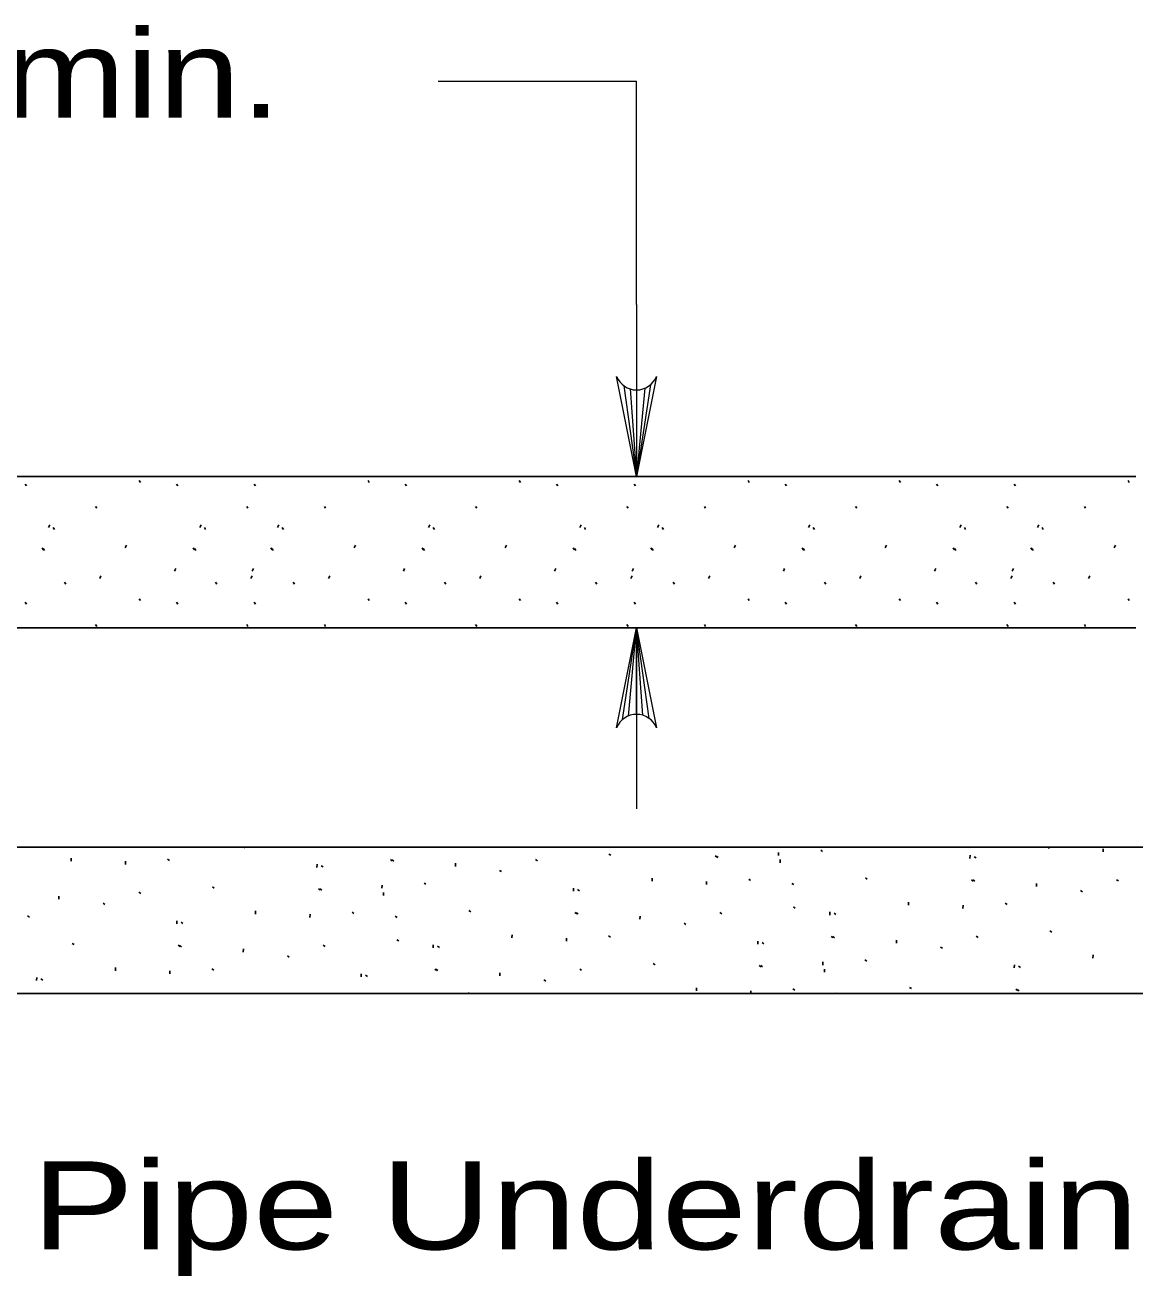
# Model space of a CAD drawing. Extents: x 1083.1 to 1117.1, y 697.4 to 741.4.
# Drawn here: x 1095.513 to 1097.478, y 711.657 to 713.873 of the extents above; entities that cross this region are included whole.
import ezdxf
from ezdxf.enums import TextEntityAlignment as Align

# ---------------------------------------------------------------- set-up
doc = ezdxf.new("R2010")
doc.units = 0
doc.header["$LTSCALE"] = 0.062
doc.layers.add('1', color=7, linetype='Continuous', lineweight=13)

msp = doc.modelspace()

# ---------------------------------------------------------------- linework, layer by layer
at = {"layer": '1'}
for p, q in [((1096.2445, 713.77358), (1096.59592, 713.77358)), ((1096.59592, 713.37825), (1096.59592, 713.77358)), ((1096.59592, 713.37825), (1096.59592, 713.07375)), ((1096.62075, 713.23592), (1096.59592, 713.07375)), ((1096.5735, 713.234), (1096.59592, 713.07375)), ((1096.58458, 713.22858), (1096.59592, 713.07375)), ((1096.61033, 713.22975), (1096.59592, 713.07375)), ((1096.59592, 713.22692), (1096.59592, 713.07375)), ((1096.57117, 712.64308), (1096.59592, 712.80517)), ((1096.58158, 712.64917), (1096.59592, 712.80517)), ((1096.59592, 712.80517), (1096.59592, 712.485)), ((1096.59592, 712.652), (1096.59592, 712.80517)), ((1096.60725, 712.65042), (1096.59592, 712.80517)), ((1096.61833, 712.64492), (1096.59592, 712.80517))]:
    msp.add_line(p, q, dxfattribs=at)
at = {"layer": '1', "lineweight": 25}
for p, q in [((1095.5135, 713.06008), (1095.51575, 713.05683)), ((1095.71517, 713.06617), (1095.71742, 713.06283)), ((1095.78117, 713.06008), (1095.7835, 713.05683)), ((1095.91867, 713.06008), (1095.921, 713.05683)), ((1096.12042, 713.06617), (1096.12258, 713.06283)), ((1096.18642, 713.06008), (1096.18867, 713.05683)), ((1096.38808, 713.06617), (1096.39033, 713.06283)), ((1096.45408, 713.06008), (1096.45633, 713.05683)), ((1096.59158, 713.06008), (1096.59392, 713.05683)), ((1096.79333, 713.06617), (1096.7955, 713.06283)), ((1096.85933, 713.06008), (1096.86158, 713.05683)), ((1097.061, 713.06617), (1097.06325, 713.06283)), ((1097.127, 713.06008), (1097.12933, 713.05683)), ((1097.2645, 713.06008), (1097.26683, 713.05683)), ((1097.46625, 713.06617), (1097.46842, 713.06283)), ((1095.63783, 713.0205), (1095.64017, 713.01708)), ((1095.90558, 713.0205), (1095.90783, 713.01708)), ((1096.04308, 713.0205), (1096.04533, 713.01708)), ((1096.31075, 713.0205), (1096.31308, 713.01708)), ((1096.5785, 713.0205), (1096.58075, 713.01708)), ((1096.716, 713.0205), (1096.71825, 713.01708)), ((1096.98367, 713.0205), (1096.986, 713.01708)), ((1097.25142, 713.0205), (1097.25367, 713.01708)), ((1097.38892, 713.0205), (1097.39117, 713.01708)), ((1095.55475, 712.98292), (1095.557, 712.988)), ((1095.56292, 712.98292), (1095.56517, 712.97967)), ((1095.8225, 712.98292), (1095.82467, 712.988)), ((1095.83058, 712.98292), (1095.83283, 712.97967)), ((1095.96, 712.98292), (1095.96217, 712.988)), ((1095.96808, 712.98292), (1095.97042, 712.97967)), ((1096.22767, 712.98292), (1096.22992, 712.988)), ((1096.23583, 712.98292), (1096.23808, 712.97967)), ((1096.49542, 712.98292), (1096.49758, 712.988)), ((1096.5035, 712.98292), (1096.50575, 712.97967)), ((1096.63292, 712.98292), (1096.63508, 712.988)), ((1096.641, 712.98292), (1096.64333, 712.97967)), ((1096.90058, 712.98292), (1096.90283, 712.988)), ((1096.90867, 712.98292), (1096.911, 712.97967)), ((1097.16833, 712.98292), (1097.1705, 712.988)), ((1097.17642, 712.98292), (1097.17867, 712.97967)), ((1097.30583, 712.98292), (1097.308, 712.988)), ((1097.31392, 712.98292), (1097.31617, 712.97967)), ((1095.69058, 712.947), (1095.69283, 712.952)), ((1096.09575, 712.947), (1096.09808, 712.952)), ((1096.3635, 712.947), (1096.36575, 712.952)), ((1096.76867, 712.947), (1096.771, 712.952)), ((1097.03642, 712.947), (1097.03867, 712.952)), ((1097.44158, 712.947), (1097.44392, 712.952)), ((1095.54308, 712.947), (1095.54525, 712.94358)), ((1095.54525, 712.94575), (1095.5475, 712.94233)), ((1095.81075, 712.947), (1095.813, 712.94358)), ((1095.813, 712.94575), (1095.81517, 712.94233)), ((1095.94825, 712.947), (1095.9505, 712.94358)), ((1095.9505, 712.94575), (1095.95267, 712.94233)), ((1096.216, 712.947), (1096.21817, 712.94358)), ((1096.21817, 712.94575), (1096.22033, 712.94233)), ((1096.48367, 712.947), (1096.48583, 712.94358)), ((1096.48583, 712.94575), (1096.48808, 712.94233)), ((1096.62117, 712.947), (1096.62342, 712.94358)), ((1096.62342, 712.94575), (1096.62558, 712.94233)), ((1096.88892, 712.947), (1096.89108, 712.94358)), ((1096.89108, 712.94575), (1096.89333, 712.94233)), ((1097.15658, 712.947), (1097.15883, 712.94358)), ((1097.15883, 712.94575), (1097.161, 712.94233)), ((1097.29408, 712.947), (1097.29633, 712.94358)), ((1097.29633, 712.94575), (1097.2985, 712.94233)), ((1095.77775, 712.9055), (1095.78, 712.91058)), ((1095.91525, 712.9055), (1095.9175, 712.91058)), ((1096.18292, 712.9055), (1096.18525, 712.91058)), ((1096.45067, 712.9055), (1096.45292, 712.91058)), ((1096.58817, 712.9055), (1096.59042, 712.91058)), ((1096.85583, 712.9055), (1096.85817, 712.91058)), ((1097.12358, 712.9055), (1097.12583, 712.91058)), ((1097.26108, 712.9055), (1097.26333, 712.91058)), ((1095.58275, 712.88617), (1095.585, 712.88283)), ((1095.64533, 712.89267), (1095.6475, 712.89775)), ((1095.8505, 712.88617), (1095.85267, 712.88283)), ((1095.913, 712.89267), (1095.91525, 712.89775)), ((1095.988, 712.88617), (1095.99017, 712.88283)), ((1096.0505, 712.89267), (1096.05275, 712.89775)), ((1096.25567, 712.88617), (1096.25792, 712.88283)), ((1096.31825, 712.89267), (1096.32042, 712.89775)), ((1096.52342, 712.88617), (1096.52558, 712.88283)), ((1096.58592, 712.89267), (1096.58817, 712.89775)), ((1096.66092, 712.88617), (1096.66308, 712.88283)), ((1096.72342, 712.89267), (1096.72567, 712.89775)), ((1096.92858, 712.88617), (1096.93083, 712.88283)), ((1096.99117, 712.89267), (1096.99333, 712.89775)), ((1097.19633, 712.88617), (1097.1985, 712.88283)), ((1097.25883, 712.89267), (1097.26108, 712.89775)), ((1097.33383, 712.88617), (1097.336, 712.88283)), ((1097.39633, 712.89267), (1097.39858, 712.89775)), ((1095.5135, 712.85083), (1095.51575, 712.84758)), ((1095.71517, 712.85692), (1095.71742, 712.85358)), ((1095.78117, 712.85083), (1095.7835, 712.84758)), ((1095.91867, 712.85083), (1095.921, 712.84758)), ((1096.12042, 712.85692), (1096.12258, 712.85358)), ((1096.18642, 712.85083), (1096.18867, 712.84758)), ((1096.38808, 712.85692), (1096.39033, 712.85358)), ((1096.45408, 712.85083), (1096.45633, 712.84758)), ((1096.59158, 712.85083), (1096.59392, 712.84758)), ((1096.79333, 712.85692), (1096.7955, 712.85358)), ((1096.85933, 712.85083), (1096.86158, 712.84758)), ((1097.061, 712.85692), (1097.06325, 712.85358)), ((1097.127, 712.85083), (1097.12933, 712.84758)), ((1097.2645, 712.85083), (1097.26683, 712.84758)), ((1097.46625, 712.85692), (1097.46842, 712.85358)), ((1095.63783, 712.81117), (1095.64017, 712.80783)), ((1095.90558, 712.81117), (1095.90783, 712.80783)), ((1096.04308, 712.81117), (1096.04533, 712.80783)), ((1096.31075, 712.81117), (1096.31308, 712.80783)), ((1096.5785, 712.81117), (1096.58075, 712.80783)), ((1096.716, 712.81117), (1096.71825, 712.80783)), ((1096.98367, 712.81117), (1096.986, 712.80783)), ((1097.25142, 712.81117), (1097.25367, 712.80783)), ((1097.38892, 712.81117), (1097.39117, 712.80783)), ((1090.79808, 712.41658), (1097.47717, 712.41658)), ((1095.90133, 712.41658), (1095.90258, 712.41575)), ((1097.32575, 712.41433), (1097.32583, 712.41658)), ((1098.92075, 712.41658), (1097.47717, 712.41658)), ((1095.5945, 712.392), (1095.59475, 712.3975)), ((1095.76558, 712.3955), (1095.76892, 712.39317)), ((1096.16008, 712.39475), (1096.16342, 712.3925)), ((1096.16258, 712.39442), (1096.16592, 712.39217)), ((1096.41683, 712.39483), (1096.42025, 712.39267)), ((1096.547, 712.40467), (1096.55042, 712.40242)), ((1096.73492, 712.40133), (1096.73817, 712.399)), ((1096.73742, 712.401), (1096.74067, 712.39867)), ((1096.84725, 712.402), (1096.8475, 712.40758)), ((1096.85, 712.38933), (1096.85017, 712.39483)), ((1096.922, 712.41133), (1096.92533, 712.409)), ((1097.18633, 712.39683), (1097.1865, 712.40233)), ((1097.19383, 712.39983), (1097.19725, 712.39767)), ((1097.42208, 712.40858), (1097.42233, 712.41408)), ((1095.69083, 712.38617), (1095.69108, 712.39175)), ((1096.03, 712.381), (1096.03017, 712.3865)), ((1096.0375, 712.384), (1096.04083, 712.38183)), ((1096.27525, 712.38275), (1096.27542, 712.38825)), ((1096.35342, 712.37575), (1096.35667, 712.3735)), ((1096.145, 712.344), (1096.14517, 712.3495)), ((1096.21967, 712.35325), (1096.223, 712.351)), ((1096.62342, 712.35633), (1096.62367, 712.36183)), ((1096.71975, 712.3505), (1096.72, 712.35608)), ((1096.7945, 712.35983), (1096.79783, 712.3575)), ((1096.871, 712.35267), (1096.87433, 712.35042)), ((1097.00108, 712.3625), (1097.0045, 712.36017)), ((1097.189, 712.35908), (1097.19225, 712.35683)), ((1097.1915, 712.35875), (1097.19475, 712.3565)), ((1097.30408, 712.34708), (1097.30425, 712.35258)), ((1097.44575, 712.35917), (1097.44908, 712.357)), ((1095.57292, 712.32467), (1095.57308, 712.33017)), ((1095.71458, 712.33683), (1095.71792, 712.33458)), ((1095.84475, 712.34658), (1095.84808, 712.34433)), ((1096.03258, 712.34325), (1096.03592, 712.341)), ((1096.03508, 712.34292), (1096.03842, 712.34058)), ((1096.14775, 712.33125), (1096.14792, 712.33675)), ((1096.48408, 712.33875), (1096.48425, 712.34425)), ((1096.49158, 712.34183), (1096.49492, 712.33958)), ((1097.38233, 712.34008), (1097.38558, 712.33783)), ((1095.65108, 712.31767), (1095.65433, 712.31542)), ((1096.87367, 712.31092), (1096.877, 712.30867)), ((1097.0775, 712.31408), (1097.07775, 712.31958)), ((1097.17383, 712.30833), (1097.17408, 712.31383)), ((1097.24858, 712.31758), (1097.25192, 712.31533)), ((1095.51742, 712.29525), (1095.52067, 712.29292)), ((1095.78175, 712.28075), (1095.78192, 712.28617)), ((1095.78925, 712.28375), (1095.79258, 712.2815)), ((1095.92117, 712.29825), (1095.92133, 712.30375)), ((1096.0175, 712.29242), (1096.01767, 712.298)), ((1096.09217, 712.30175), (1096.0955, 712.29942)), ((1096.16867, 712.29458), (1096.172, 712.29233)), ((1096.29883, 712.30442), (1096.30217, 712.30208)), ((1096.48667, 712.30108), (1096.49, 712.29875)), ((1096.48917, 712.30067), (1096.4925, 712.29842)), ((1096.60183, 712.289), (1096.602, 712.2945)), ((1096.7435, 712.30108), (1096.74683, 712.29892)), ((1096.93817, 712.29658), (1096.93833, 712.30208)), ((1096.94567, 712.29958), (1096.949, 712.29742)), ((1096.37525, 712.256), (1096.37542, 712.2615)), ((1096.68, 712.282), (1096.68325, 712.27975)), ((1097.32775, 712.26875), (1097.33108, 712.26642)), ((1095.5965, 712.24633), (1095.59992, 712.24408)), ((1095.78433, 712.243), (1095.78767, 712.24067)), ((1095.78683, 712.24267), (1095.79017, 712.24033)), ((1096.04117, 712.24308), (1096.0445, 712.24083)), ((1096.17133, 712.25292), (1096.17467, 712.25058)), ((1096.23583, 712.2385), (1096.236, 712.244)), ((1096.24333, 712.2415), (1096.24675, 712.23933)), ((1096.47158, 712.25025), (1096.47183, 712.25575)), ((1096.54625, 712.25958), (1096.54958, 712.25725)), ((1096.81067, 712.24508), (1096.81083, 712.2505)), ((1096.81817, 712.24808), (1096.8215, 712.24583)), ((1096.94075, 712.25883), (1096.94408, 712.2565)), ((1096.94325, 712.2585), (1096.94658, 712.25617)), ((1097.05592, 712.24683), (1097.05608, 712.25233)), ((1097.13408, 712.23975), (1097.13742, 712.23758)), ((1097.19758, 712.25892), (1097.20092, 712.25667)), ((1095.8995, 712.231), (1095.89967, 712.2365)), ((1095.97767, 712.224), (1095.981, 712.22175)), ((1097.00042, 712.21733), (1097.00367, 712.215)), ((1097.40408, 712.22033), (1097.40433, 712.22592)), ((1095.67292, 712.198), (1095.67317, 712.2035)), ((1095.76925, 712.19217), (1095.7695, 712.19767)), ((1095.844, 712.2015), (1095.84725, 712.19917)), ((1096.23842, 712.20075), (1096.24175, 712.1985)), ((1096.241, 712.20042), (1096.24425, 712.19808)), ((1096.49525, 712.20083), (1096.49858, 712.19867)), ((1096.62542, 712.21067), (1096.62883, 712.20842)), ((1096.81325, 712.20733), (1096.81658, 712.205)), ((1096.81575, 712.207), (1096.81908, 712.20467)), ((1096.92567, 712.208), (1096.92592, 712.2135)), ((1096.92842, 712.19533), (1096.92858, 712.20083)), ((1097.26475, 712.20283), (1097.26492, 712.20833)), ((1097.27225, 712.20583), (1097.27558, 712.20367)), ((1095.53358, 712.18042), (1095.53367, 712.18592)), ((1095.54108, 712.1835), (1095.54442, 712.18125)), ((1096.10833, 712.187), (1096.1085, 712.1925)), ((1096.11592, 712.19), (1096.11925, 712.18783)), ((1096.35358, 712.18875), (1096.35375, 712.19425)), ((1096.43175, 712.18175), (1096.43508, 712.1795)), ((1097.47717, 712.15767), (1090.81242, 712.15767)), ((1096.29808, 712.15925), (1096.30033, 712.15767)), ((1096.70183, 712.16225), (1096.70208, 712.16783)), ((1096.79825, 712.15767), (1096.79842, 712.162)), ((1096.87283, 712.16583), (1096.87617, 712.1635)), ((1096.94933, 712.15858), (1096.95075, 712.15767)), ((1097.0795, 712.16842), (1097.08292, 712.16617)), ((1097.26733, 712.16508), (1097.27067, 712.16275)), ((1097.26983, 712.16475), (1097.27317, 712.16242)), ((1097.38267, 712.15767), (1097.38267, 712.15858))]:
    msp.add_line(p, q, dxfattribs=at)
at = {"layer": '1'}
for points in [[(1096.63133, 713.25075), (1096.59592, 713.07375), (1096.56058, 713.25075)], [(1096.56058, 712.62817), (1096.59592, 712.80517), (1096.63133, 712.62817)]]:
    msp.add_lwpolyline(points, dxfattribs=at)
at = {"layer": '1', "lineweight": 25}
for points in [[(1097.47983, 713.07375), (1090.79808, 713.07375), (1090.79808, 712.80517), (1097.47983, 712.80517)], [(1097.47717, 712.15767), (1098.92075, 712.15767), (1098.92075, 713.07375), (1098.92075, 712.41658)]]:
    msp.add_lwpolyline(points, dxfattribs=at)
at = {"layer": '1'}
for centre, start, end in [((1096.59591, 713.26506), 202.08782, 337.91395), ((1096.59599, 712.61391), 22.08782, 157.91395)]:
    msp.add_arc(centre, 0.0382, start, end, dxfattribs=at)

# ---------------------------------------------------------------- texts
at = {"layer": '1', "width": 1.25}
msp.add_text('4" [100] min.', height=0.156, dxfattribs=at).set_placement((1095.23929, 713.709), align=Align.CENTER)
at = {"layer": '1', "width": 1.3}
msp.add_text('Pipe Underdrain', height=0.156, dxfattribs=at).set_placement((1095.52492, 711.70417))

doc.saveas('drawing.dxf')
